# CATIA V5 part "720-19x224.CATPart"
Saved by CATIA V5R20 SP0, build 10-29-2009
Part number: 720-19x224
Definition: NONE
Nomenclature: 720-19x224
Source: Unknown
Description: 720-19x224
Bounding box of the stored display mesh (mm): x 0 to 224, y -9.5 to 9.5, z -9.5 to 9.5
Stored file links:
  C:\Users\Utente\Desktop\IO LAVORO\3D X SITO CF\X SITO\720\720-19x224.CATPart
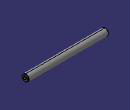
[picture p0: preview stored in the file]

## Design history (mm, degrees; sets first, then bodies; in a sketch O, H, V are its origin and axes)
Body1 "720-19x224" (main body)
  Solid1: solid without history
